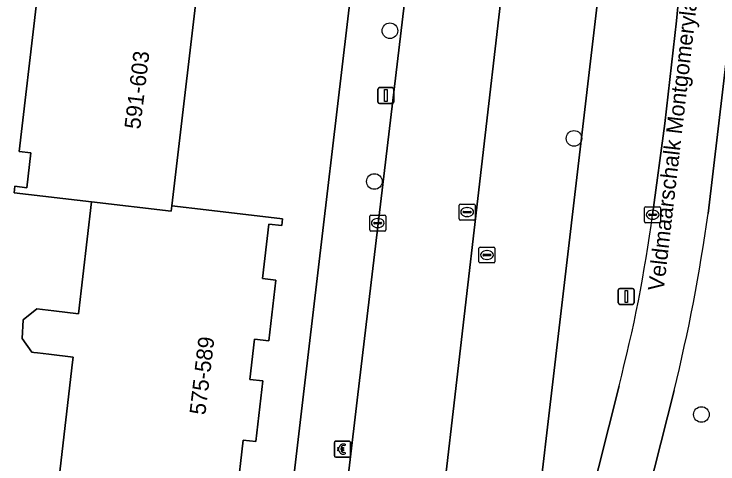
# Model space of a CAD drawing. Extents: x 160856 to 161310, y 384024 to 384878.
# Drawn here: x 161229.28 to 161273.37, y 384605.63 to 384633.8 of the extents above; entities that cross this region are included whole.
import ezdxf

# ---------------------------------------------------------------- set-up
doc = ezdxf.new("R2010")
doc.units = 0
for name, color, linetype in [('IMGEO_Berm_groen', 7, 'Continuous'), ('IMGEO_Betaalautomaat', 7, 'Continuous'), ('IMGEO_Boom', 7, 'Continuous'), ('IMGEO_Erf', 7, 'Continuous'), ('IMGEO_Kolk', 7, 'Continuous'), ('IMGEO_Lichtmast', 7, 'Continuous'), ('IMGEO_Openbare_ruimte_label', 7, 'Continuous'), ('IMGEO_Pand', 7, 'Continuous'), ('IMGEO_Pand_nummerreeks', 7, 'Continuous'), ('IMGEO_Parkeervlak_open', 7, 'Continuous'), ('IMGEO_Rijbaan_lokaal_gesloten', 7, 'Continuous'), ('IMGEO_Rijbaan_lokaal_open', 7, 'Continuous'), ('IMGEO_Rioolput', 7, 'Continuous'), ('IMGEO_Voetpad_open', 7, 'Continuous')]:
    doc.layers.add(name, color=color, linetype=linetype)

msp = doc.modelspace()

# ---------------------------------------------------------------- linework, layer by layer
at = {"layer": 'IMGEO_Berm_groen'}
for points in [[(161271.226, 384656.034), (161271.075, 384657.442), (161268.546, 384657.7), (161262.738, 384608.287), (161261.545, 384598.151), (161258.141, 384567.697), (161257.931, 384565.814), (161257.361, 384560.886), (161251.303, 384561.613), (161250.737, 384556.74), (161256.785, 384556.041), (161251.596, 384511.132), (161250.377, 384500), (161238.15, 384396.266), (161238.006, 384395.04), (161236.799, 384395.17)], [(161276.84, 384656.028), (161276.831, 384655.949), (161276.778, 384655.441), (161272.75, 384621.314)], [(161269.278, 384621.237), (161270.042, 384626.946), (161270.768, 384633.387), (161271.177, 384637.579), (161271.463, 384640.515)], [(161263.827, 384596.548), (161264.307, 384598.77), (161264.588, 384600.259), (161267.173, 384610.524)], [(161270.621, 384610.235), (161268.554, 384602.069)]]:
    msp.add_lwpolyline(points, dxfattribs=at)
for centre, radius, start, end in [((161178.22, 384633.566), 91.889, 345.47773, 352.28938), ((161168.311, 384635.64), 105.417, 346.05499, 352.18969)]:
    msp.add_arc(centre, radius, start, end, dxfattribs=at)
at = {"layer": 'IMGEO_Betaalautomaat'}
for p, q in [((161249.423, 384607.062), (161250.264, 384607.062)), ((161250.264, 384607.062), (161249.423, 384607.062)), ((161249.348, 384606.138), (161249.348, 384606.979)), ((161249.348, 384606.979), (161249.348, 384606.138)), ((161249.631, 384606.526), (161249.631, 384606.594)), ((161249.752, 384606.594), (161249.752, 384606.526)), ((161250.01, 384606.867), (161249.993, 384606.767)), ((161250.347, 384606.988), (161250.347, 384606.147)), ((161250.347, 384606.147), (161250.347, 384606.988)), ((161249.997, 384606.361), (161250.019, 384606.274)), ((161250.273, 384606.063), (161249.432, 384606.063)), ((161249.432, 384606.063), (161250.273, 384606.063))]:
    msp.add_line(p, q, dxfattribs=at)
for points in [[(161249.631, 384606.594), (161249.562, 384606.594), (161249.562, 384606.663), (161249.641, 384606.663)], [(161249.763, 384606.663), (161249.91, 384606.663), (161249.91, 384606.594), (161249.752, 384606.594)], [(161249.636, 384606.457), (161249.562, 384606.457), (161249.562, 384606.526), (161249.631, 384606.526)], [(161249.752, 384606.526), (161249.91, 384606.526), (161249.91, 384606.457), (161249.766, 384606.457)]]:
    msp.add_lwpolyline(points, dxfattribs=at)
for centre, radius, start, end in [((161249.426, 384606.985), 0.0779, 92.4484, 184.2845), ((161249.426, 384606.985), 0.0779, 92.4484, 184.2845), ((161250.27, 384606.985), 0.0779, 2.4484, 94.2845), ((161250.27, 384606.985), 0.0779, 2.4484, 94.2845), ((161249.924, 384606.587), 0.293, 73.014, 165.0139), ((161249.93, 384606.6), 0.179, 69.3236, 159.5683), ((161249.897, 384606.512), 0.267, 191.8096, 297.0389), ((161249.93, 384606.527), 0.179, 202.7625, 291.8693), ((161249.426, 384606.141), 0.0779, 182.4484, 274.2845), ((161249.426, 384606.141), 0.0779, 182.4484, 274.2845), ((161250.27, 384606.141), 0.0779, 272.4484, 4.2845), ((161250.27, 384606.141), 0.0779, 272.4484, 4.2845)]:
    msp.add_arc(centre, radius, start, end, dxfattribs=at)
at = {"layer": 'IMGEO_Boom'}
for centre in [(161252.822, 384632.757), (161264.353, 384626.014), (161251.848, 384623.316), (161272.333, 384608.727)]:
    msp.add_circle(centre, 0.489, dxfattribs=at)
at = {"layer": 'IMGEO_Erf'}
for points in [[(161242.554, 384568.674), (161247.412, 384609.996), (161250.719, 384638.124), (161250.156, 384638.19), (161250.196, 384638.529), (161244.925, 384638.343), (161244.891, 384638.051), (161243.138, 384637.94), (161243.111, 384637.713), (161241.057, 384637.954), (161239.167, 384621.793), (161241.313, 384621.542), (161246.096, 384620.983), (161246.046, 384620.558), (161245.234, 384620.653), (161244.835, 384617.245), (161245.686, 384617.145), (161245.242, 384613.347), (161244.346, 384613.452), (161244.05, 384610.921), (161244.863, 384610.826), (161244.419, 384607.029), (161243.634, 384607.121), (161243.228, 384603.648)], [(161232.099, 384604.776), (161232.945, 384612.002), (161232.982, 384612.32), (161231.452, 384612.499), (161230.749, 384612.581), (161230.508, 384612.609), (161230.392, 384612.623), (161229.789, 384613.483), (161229.854, 384614.658), (161230.71, 384615.344), (161231.771, 384615.22), (161233.307, 384615.04), (161234.126, 384622.045), (161229.28, 384622.612), (161229.327, 384623.015), (161230.073, 384622.927), (161230.328, 384625.106), (161229.589, 384625.192), (161230.655, 384634.305)]]:
    msp.add_lwpolyline(points, dxfattribs=at)
at = {"layer": 'IMGEO_Kolk'}
for p, q in [((161257.161, 384620.977), (161257.161, 384621.829)), ((161257.236, 384621.903), (161258.088, 384621.903)), ((161257.649, 384621.683), (161257.674, 384621.683)), ((161258.162, 384621.829), (161258.162, 384620.977)), ((161268.777, 384620.811), (161268.777, 384621.663)), ((161268.852, 384621.737), (161269.704, 384621.737)), ((161269.778, 384621.663), (161269.778, 384620.811)), ((161251.636, 384621.213), (161252.488, 384621.213)), ((161257.42, 384621.397), (161257.42, 384621.409)), ((161257.858, 384621.36), (161257.46, 384621.36)), ((161257.463, 384621.446), (161257.861, 384621.446)), ((161257.904, 384621.409), (161257.904, 384621.397)), ((161269.036, 384621.231), (161269.036, 384621.243)), ((161269.474, 384621.194), (161269.076, 384621.194)), ((161269.079, 384621.28), (161269.477, 384621.28)), ((161269.265, 384621.517), (161269.29, 384621.517)), ((161269.52, 384621.243), (161269.52, 384621.231)), ((161251.561, 384620.287), (161251.561, 384621.139)), ((161251.82, 384620.707), (161251.82, 384620.719)), ((161251.863, 384620.756), (161252.261, 384620.756)), ((161252.049, 384620.993), (161252.074, 384620.993)), ((161252.304, 384620.719), (161252.304, 384620.707)), ((161252.562, 384621.139), (161252.562, 384620.287)), ((161258.088, 384620.903), (161257.236, 384620.903)), ((161257.672, 384621.123), (161257.647, 384621.123)), ((161269.704, 384620.737), (161268.852, 384620.737)), ((161269.288, 384620.957), (161269.263, 384620.957)), ((161252.258, 384620.67), (161251.86, 384620.67)), ((161252.072, 384620.433), (161252.047, 384620.433)), ((161252.488, 384620.213), (161251.636, 384620.213))]:
    msp.add_line(p, q, dxfattribs=at)
for points in [[(161257.161, 384620.977), (161257.161, 384621.829)], [(161257.236, 384621.903), (161258.088, 384621.903)], [(161258.162, 384621.829), (161258.162, 384620.977)], [(161268.777, 384620.811), (161268.777, 384621.663)], [(161268.852, 384621.737), (161269.704, 384621.737)], [(161269.778, 384621.663), (161269.778, 384620.811)], [(161251.636, 384621.213), (161252.488, 384621.213)], [(161251.561, 384620.287), (161251.561, 384621.139)], [(161252.562, 384621.139), (161252.562, 384620.287)], [(161258.088, 384620.903), (161257.236, 384620.903)], [(161269.704, 384620.737), (161268.852, 384620.737)], [(161252.488, 384620.213), (161251.636, 384620.213)]]:
    msp.add_lwpolyline(points, dxfattribs=at)
for centre, radius, start, end in [((161257.238, 384621.827), 0.0765, 91.552, 178.448), ((161257.238, 384621.827), 0.0765, 91.552, 178.448), ((161258.086, 384621.827), 0.0765, 1.552, 88.448), ((161258.086, 384621.827), 0.0765, 1.552, 88.448), ((161268.854, 384621.661), 0.0765, 91.552, 178.448), ((161268.854, 384621.661), 0.0765, 91.552, 178.448), ((161269.702, 384621.661), 0.0765, 1.552, 88.448), ((161269.702, 384621.661), 0.0765, 1.552, 88.448), ((161251.638, 384621.137), 0.0765, 91.552, 178.448), ((161251.638, 384621.137), 0.0765, 91.552, 178.448), ((161252.486, 384621.137), 0.0765, 1.552, 88.448), ((161252.486, 384621.137), 0.0765, 1.552, 88.448), ((161257.46, 384621.406), 0.0403, 85.8775, 175.7526), ((161257.457, 384621.396), 0.0366, 178.938, 274.7102), ((161257.861, 384621.403), 0.043, 264.8664, 352.4533), ((161257.865, 384621.408), 0.0386, 1.7309, 96.639), ((161269.076, 384621.24), 0.0403, 85.8775, 175.7526), ((161269.073, 384621.23), 0.0366, 178.938, 274.7102), ((161269.477, 384621.237), 0.043, 264.8664, 352.4533), ((161269.481, 384621.242), 0.0386, 1.7309, 96.639), ((161251.86, 384620.716), 0.0403, 85.8775, 175.7526), ((161251.857, 384620.706), 0.0366, 178.938, 274.7102), ((161252.261, 384620.713), 0.043, 264.8664, 352.4533), ((161252.265, 384620.718), 0.0386, 1.7309, 96.639), ((161257.238, 384620.979), 0.0765, 181.552, 268.448), ((161257.238, 384620.979), 0.0765, 181.552, 268.448), ((161258.086, 384620.979), 0.0765, 271.552, 358.448), ((161258.086, 384620.979), 0.0765, 271.552, 358.448), ((161268.854, 384620.813), 0.0765, 181.552, 268.448), ((161268.854, 384620.813), 0.0765, 181.552, 268.448), ((161269.702, 384620.813), 0.0765, 271.552, 358.448), ((161269.702, 384620.813), 0.0765, 271.552, 358.448), ((161251.638, 384620.289), 0.0765, 181.552, 268.448), ((161251.638, 384620.289), 0.0765, 181.552, 268.448), ((161252.486, 384620.289), 0.0765, 271.552, 358.448), ((161252.486, 384620.289), 0.0765, 271.552, 358.448)]:
    msp.add_arc(centre, radius, start, end, dxfattribs=at)
for centre, major_axis, ratio, start_param, end_param in [((161257.648, 384621.403), (-0.387, 0.002), 0.722429, 4.712389, 7.853982), ((161257.673, 384621.403), (-0.39, 0.002), 0.717154, 1.570796, 4.712389), ((161269.264, 384621.237), (-0.387, 0.002), 0.722429, 4.712389, 7.853982), ((161269.289, 384621.237), (-0.39, 0.002), 0.717154, 1.570796, 4.712389), ((161252.048, 384620.713), (-0.387, 0.002), 0.722429, 4.712389, 7.853982), ((161252.073, 384620.713), (-0.39, 0.002), 0.717154, 1.570796, 4.712389)]:
    msp.add_ellipse(centre, major_axis=major_axis, ratio=ratio, start_param=start_param, end_param=end_param, dxfattribs=at)
at = {"layer": 'IMGEO_Lichtmast'}
for p, q in [((161252.07, 384628.295), (161252.07, 384629.095)), ((161252.07, 384629.095), (161252.07, 384628.295)), ((161252.17, 384629.195), (161252.96, 384629.195)), ((161252.96, 384629.195), (161252.17, 384629.195)), ((161253.06, 384629.095), (161253.06, 384628.295)), ((161253.06, 384628.295), (161253.06, 384629.095)), ((161252.96, 384628.195), (161252.17, 384628.195)), ((161252.17, 384628.195), (161252.96, 384628.195)), ((161267.13, 384615.724), (161267.13, 384616.524)), ((161267.13, 384616.524), (161267.13, 384615.724)), ((161267.23, 384616.624), (161268.02, 384616.624)), ((161268.02, 384616.624), (161267.23, 384616.624)), ((161268.12, 384616.524), (161268.12, 384615.724)), ((161268.12, 384615.724), (161268.12, 384616.524)), ((161268.02, 384615.624), (161267.23, 384615.624)), ((161267.23, 384615.624), (161268.02, 384615.624))]:
    msp.add_line(p, q, dxfattribs=at)
for points in [[(161252.49, 384629.07), (161252.64, 384629.07), (161252.64, 384628.32), (161252.49, 384628.32), (161252.49, 384629.07)], [(161267.55, 384616.499), (161267.7, 384616.499), (161267.7, 384615.749), (161267.55, 384615.749), (161267.55, 384616.499)]]:
    msp.add_lwpolyline(points, dxfattribs=at)
for centre, start, end in [((161252.17, 384629.095), 90, 180), ((161252.17, 384629.095), 90, 180), ((161252.96, 384629.095), 0, 90), ((161252.96, 384629.095), 360, 90), ((161252.17, 384628.295), 180, 270), ((161252.17, 384628.295), 180, 270), ((161252.96, 384628.295), 270, 0), ((161252.96, 384628.295), 270, 0), ((161267.23, 384616.524), 90, 180), ((161267.23, 384616.524), 90, 180), ((161268.02, 384616.524), 0, 90), ((161268.02, 384616.524), 360, 90), ((161267.23, 384615.724), 180, 270), ((161267.23, 384615.724), 180, 270), ((161268.02, 384615.724), 270, 0), ((161268.02, 384615.724), 270, 0)]:
    msp.add_arc(centre, 0.1, start, end, dxfattribs=at)
at = {"layer": 'IMGEO_Pand'}
for points in [[(161230.655, 384634.305), (161229.589, 384625.192), (161230.328, 384625.106), (161230.073, 384622.927), (161229.327, 384623.015), (161229.28, 384622.612), (161234.126, 384622.045), (161239.128, 384621.46), (161239.167, 384621.793), (161241.057, 384637.954)], [(161243.228, 384603.648), (161243.634, 384607.121), (161244.419, 384607.029), (161244.863, 384610.826), (161244.05, 384610.921), (161244.346, 384613.452), (161245.242, 384613.347), (161245.686, 384617.145), (161244.835, 384617.245), (161245.234, 384620.653), (161246.046, 384620.558), (161246.096, 384620.983), (161241.313, 384621.542), (161239.167, 384621.793), (161239.128, 384621.46), (161234.126, 384622.045), (161233.307, 384615.04), (161231.771, 384615.22), (161230.71, 384615.344), (161229.854, 384614.658), (161229.789, 384613.483), (161230.392, 384612.623), (161230.508, 384612.609), (161230.749, 384612.581), (161231.452, 384612.499), (161232.982, 384612.32), (161232.945, 384612.002), (161232.099, 384604.776)]]:
    msp.add_lwpolyline(points, dxfattribs=at)
at = {"layer": 'IMGEO_Parkeervlak_open'}
for points in [[(161268.546, 384657.7), (161262.507, 384658.314), (161251.981, 384567.454)], [(161253.185, 384568.246), (161258.141, 384567.697), (161261.545, 384598.151), (161262.738, 384608.287), (161268.546, 384657.7)]]:
    msp.add_lwpolyline(points, dxfattribs=at)
at = {"layer": 'IMGEO_Rijbaan_lokaal_gesloten'}
for points in [[(161272.75, 384621.314), (161276.778, 384655.441), (161276.831, 384655.949), (161276.84, 384656.028), (161277.189, 384659.033), (161277.558, 384662.212), (161277.881, 384664.847)], [(161271.463, 384640.515), (161271.177, 384637.579), (161270.768, 384633.387), (161270.042, 384626.946), (161269.278, 384621.237)], [(161267.173, 384610.524), (161264.588, 384600.259), (161264.307, 384598.77), (161263.827, 384596.548)], [(161268.554, 384602.069), (161270.621, 384610.235)]]:
    msp.add_lwpolyline(points, dxfattribs=at)
for centre, radius, start, end in [((161178.22, 384633.566), 91.889, 345.47773, 352.28938), ((161168.311, 384635.64), 105.417, 346.05499, 352.18969)]:
    msp.add_arc(centre, radius, start, end, dxfattribs=at)
at = {"layer": 'IMGEO_Rijbaan_lokaal_open'}
for points in [[(161250.737, 384556.74), (161251.303, 384561.613), (161251.981, 384567.454), (161262.507, 384658.314)], [(161253.842, 384635.509), (161253.738, 384634.519), (161250.766, 384609.622), (161249.855, 384601.831), (161243.381, 384545.472), (161239.778, 384514.805), (161238.057, 384500), (161237.777, 384496.96), (161237.656, 384495.995), (161237.846, 384495.256), (161238.878, 384493.86)]]:
    msp.add_lwpolyline(points, dxfattribs=at)
at = {"layer": 'IMGEO_Rioolput'}
for p, q in [((161258.401, 384618.288), (161258.401, 384619.14)), ((161258.476, 384619.214), (161259.328, 384619.214)), ((161258.889, 384618.994), (161258.914, 384618.994)), ((161259.402, 384619.14), (161259.402, 384618.288)), ((161258.66, 384618.708), (161258.66, 384618.72)), ((161259.098, 384618.671), (161258.7, 384618.671)), ((161258.703, 384618.757), (161259.101, 384618.757)), ((161259.144, 384618.72), (161259.144, 384618.708)), ((161259.328, 384618.214), (161258.476, 384618.214)), ((161258.912, 384618.434), (161258.887, 384618.434))]:
    msp.add_line(p, q, dxfattribs=at)
for points in [[(161258.401, 384618.288), (161258.401, 384619.14)], [(161258.476, 384619.214), (161259.328, 384619.214)], [(161259.402, 384619.14), (161259.402, 384618.288)], [(161259.328, 384618.214), (161258.476, 384618.214)]]:
    msp.add_lwpolyline(points, dxfattribs=at)
for centre, radius, start, end in [((161258.478, 384619.138), 0.0765, 91.552, 178.448), ((161258.478, 384619.138), 0.0765, 91.552, 178.448), ((161259.326, 384619.138), 0.0765, 1.552, 88.448), ((161259.326, 384619.138), 0.0765, 1.552, 88.448), ((161258.7, 384618.717), 0.0403, 85.8775, 175.7526), ((161258.697, 384618.707), 0.0366, 178.938, 274.7102), ((161259.101, 384618.714), 0.043, 264.8664, 352.4533), ((161259.105, 384618.719), 0.0386, 1.7309, 96.639), ((161258.478, 384618.29), 0.0765, 181.552, 268.448), ((161258.478, 384618.29), 0.0765, 181.552, 268.448), ((161259.326, 384618.29), 0.0765, 271.552, 358.448), ((161259.326, 384618.29), 0.0765, 271.552, 358.448)]:
    msp.add_arc(centre, radius, start, end, dxfattribs=at)
for centre, major_axis, ratio, start_param, end_param in [((161258.888, 384618.714), (-0.387, 0.002), 0.722429, 4.712389, 7.853982), ((161258.913, 384618.714), (-0.39, 0.002), 0.717154, 1.570796, 4.712389)]:
    msp.add_ellipse(centre, major_axis=major_axis, ratio=ratio, start_param=start_param, end_param=end_param, dxfattribs=at)
at = {"layer": 'IMGEO_Voetpad_open'}
for points in [[(161255.213, 384668.454), (161253.755, 384663.908), (161251.223, 384642.435), (161250.719, 384638.124), (161247.412, 384609.996), (161242.554, 384568.674), (161242.07, 384564.539), (161234.582, 384500)], [(161243.381, 384545.472), (161249.855, 384601.831), (161250.766, 384609.622), (161253.738, 384634.519), (161253.842, 384635.509), (161254.139, 384638.175), (161253.156, 384638.287), (161253.346, 384639.957), (161254.326, 384639.846), (161254.652, 384642.767), (161254.663, 384642.875), (161254.769, 384643.763), (161256.647, 384659.845)]]:
    msp.add_lwpolyline(points, dxfattribs=at)

# ---------------------------------------------------------------- texts
at = {"layer": 'IMGEO_Openbare_ruimte_label'}
msp.add_text('Veldmaarschalk Montgomerylaan', height=1, rotation=83.394, dxfattribs=at).set_placement((161269.969, 384616.425))
at = {"layer": 'IMGEO_Pand_nummerreeks'}
for s, rotation, p in [('591-603', 83.0888, (161237.177, 384626.555)), ('575-589', 83.1706, (161241.255, 384608.666))]:
    msp.add_text(s, height=1, rotation=rotation, dxfattribs=at).set_placement(p)

doc.saveas('drawing.dxf')
